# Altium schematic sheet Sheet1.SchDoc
size A4; SheetNumber: 1; SheetTotal: 1
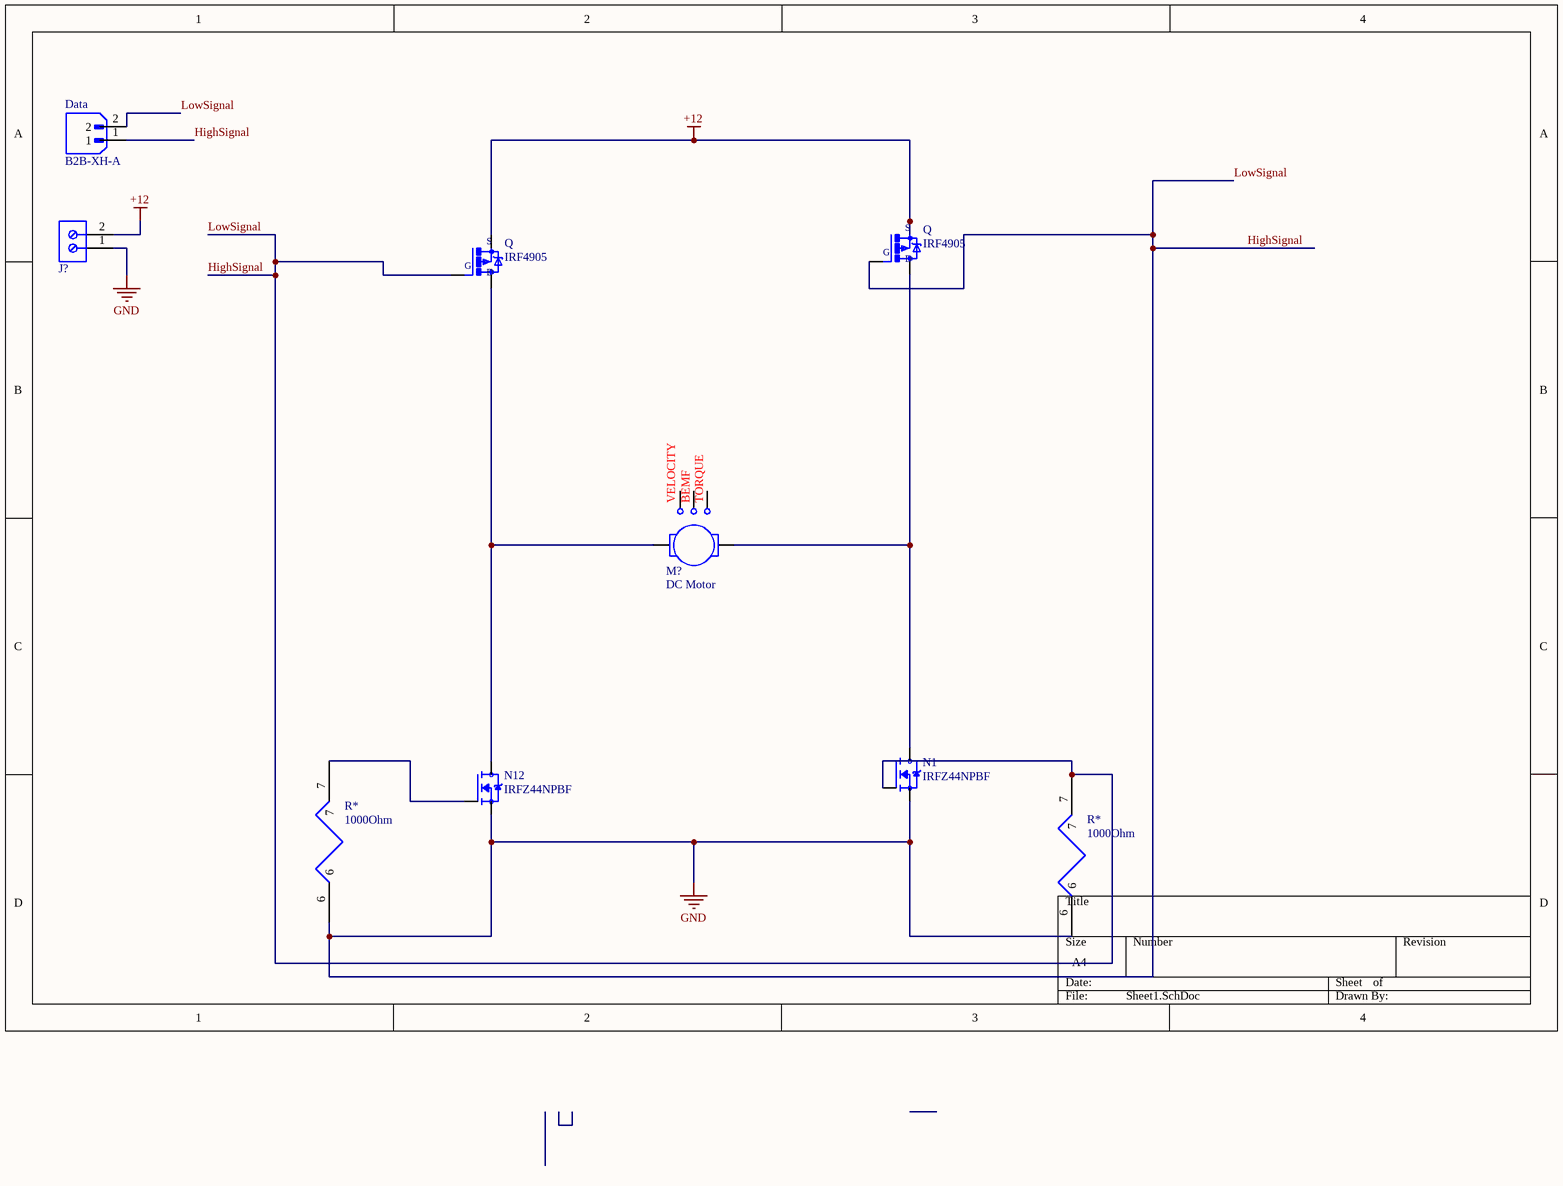
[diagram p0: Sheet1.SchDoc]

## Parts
(Parts that share a designator on the sheet are numbered #1, #2 ... from top to bottom, then left to right.)
Data  B2B-XH-A  [JST_B2B-XH-A]
J?  691101710002  [691305530002]  (value not drawn)
M?  DC Motor
N1  IRFZ44NPBF  [TO254P1016X419X2286-3]
N12  IRFZ44NPBF  [TO254P1016X419X2286-3]
Q#1  IRF4905  [TO220BH]
Q#2  IRF4905  [TO220BH]
R*#1  1000Ohm  [RESAD1100W55L680D260]
R*#2  1000Ohm  [RESAD1100W55L680D260]

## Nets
+12: J?.2 Q#1.S Q#2.S
HighSignal: Data.1 Data.2 J?.1 N1.1(G) N1.3(S) N12.3(S) Q#1.G Q#2.G R*#1.6 R*#2.6 R*#2.7  [also labelled GND, LowSignal]
NetM?_1: M?.1 N12.2(D) Q#2.D
NetM?_2: M?.2 N1.2(D) Q#1.D
NetN12_1: N12.1(G) R*#1.7

Not connected (* = marked no-connect by the designer): M? 3 4 5

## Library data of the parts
Data = B2B-XH-A: MF: {'manufacturer': u'JST Sales America Inc.'}
J? = 691101710002: WR-TBL Series 101 Horizontal Entry Modular, THT, pitch 5mm, 2p; Manufacturer: Wurth Elektronik; Modularity: Yes; Rated Current: 16A; Working Voltage: 250V
M? = DC Motor: LA: 1.5M; RA: 0.5; KE: 0.05; JM: 250U; BM: 0.1M; TL: 0; SimulationGenericComponent: True
N1 N12 = IRFZ44NPBF: N-Channel 55 V 49A (Tc) 94W (Tc) Through Hole TO-220AB; MF: Infineon
Q#1 Q#2 = IRF4905: P-Channel 55V 74A _Tc_ 200W _Tc_ Through Hole TO-220AB; MF: Infineon Technologies
R*#1 R*#2 = Component_1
